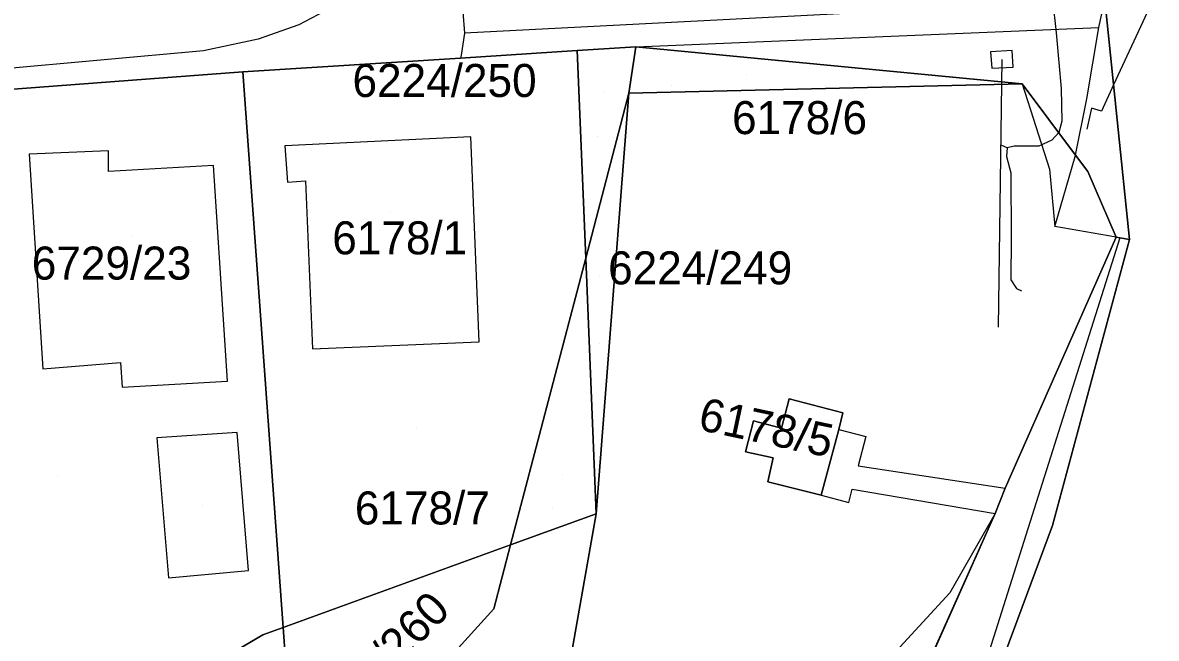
# Model space of a CAD drawing. Extents: x -266199 to -261993, y -1239047 to -1235108.
# Drawn here: x -263970.2 to -263901.5, y -1236261.5 to -1236224.3 of the extents above; entities that cross this region are included whole.
import ezdxf

# ---------------------------------------------------------------- set-up
doc = ezdxf.new("R2010")
doc.units = 0
for name, color, linetype in [('body_kn', 7, 'Continuous'), ('kladpar_druhypozemkov', 7, 'Continuous'), ('kladpar_hranice', 7, 'Continuous'), ('kladpar_parcelnecisla', 7, 'Continuous'), ('kladpar_plochy', 7, 'Continuous'), ('kladpar_sipky', 7, 'Continuous'), ('linie', 7, 'Continuous'), ('tarchy_linie', 7, 'Continuous'), ('zappar_hrandruhpozemk', 7, 'Continuous')]:
    doc.layers.add(name, color=color, linetype=linetype)

msp = doc.modelspace()

# ---------------------------------------------------------------- linework, layer by layer
at = {"layer": 'body_kn'}
for p, q in [((-263953.46, -1236224.39), (-263953.46, -1236224.39)), ((-263943.43, -1236224.89), (-263943.43, -1236224.89)), ((-263907.61, -1236224.67), (-263907.61, -1236224.67)), ((-263905.01, -1236224.56), (-263905.01, -1236224.56)), ((-263905.01, -1236224.56), (-263905.01, -1236224.56)), ((-263955.93, -1236225.26), (-263955.93, -1236225.26)), ((-263907.56, -1236225.09), (-263907.56, -1236225.09)), ((-263959.24, -1236225.96), (-263959.24, -1236225.96)), ((-263943.64, -1236226.23), (-263943.64, -1236226.23)), ((-263936.6, -1236225.95), (-263936.6, -1236225.95)), ((-263936.6, -1236225.95), (-263936.6, -1236225.95)), ((-263933.05, -1236225.73), (-263933.05, -1236225.73)), ((-263933.05, -1236225.73), (-263933.05, -1236225.73)), ((-263911.56, -1236226.02), (-263911.56, -1236226.02)), ((-263911.56, -1236226.02), (-263911.56, -1236226.02)), ((-263910.25, -1236225.94), (-263910.25, -1236225.94)), ((-263943.67, -1236226.4), (-263943.67, -1236226.4)), ((-263910.88, -1236226.48), (-263910.88, -1236226.48)), ((-263910.19, -1236226.95), (-263910.19, -1236226.95)), ((-263956.86, -1236227.23), (-263956.86, -1236227.23)), ((-263956.86, -1236227.23), (-263956.86, -1236227.23)), ((-263911.49, -1236227.01), (-263911.49, -1236227.01)), ((-263909.64, -1236227.97), (-263909.64, -1236227.97)), ((-263909.64, -1236227.97), (-263909.64, -1236227.97)), ((-263907.28, -1236228.25), (-263907.28, -1236228.25)), ((-263904.11, -1236228.02), (-263904.11, -1236228.02)), ((-263933.47, -1236228.53), (-263933.47, -1236228.53)), ((-263933.47, -1236228.53), (-263933.47, -1236228.53)), ((-263905.74, -1236228.87), (-263905.74, -1236228.87)), ((-263905.45, -1236229.43), (-263905.45, -1236229.43)), ((-263904.85, -1236229.61), (-263904.85, -1236229.61)), ((-263907.25, -1236230.23), (-263907.25, -1236230.23)), ((-263907.43, -1236230.92), (-263907.43, -1236230.92)), ((-263907.43, -1236230.92), (-263907.43, -1236230.92)), ((-263905.74, -1236230.7), (-263905.74, -1236230.7)), ((-263954.32, -1236231.72), (-263954.32, -1236231.72)), ((-263943.05, -1236231.17), (-263943.05, -1236231.17)), ((-263910.87, -1236231.7), (-263910.87, -1236231.7)), ((-263910.14, -1236231.74), (-263910.14, -1236231.74)), ((-263908.64, -1236231.73), (-263908.64, -1236231.73)), ((-263907.85, -1236231.37), (-263907.85, -1236231.37)), ((-263969.8, -1236232.23), (-263969.8, -1236232.23)), ((-263965.01, -1236232.02), (-263965.01, -1236232.02)), ((-263910.59, -1236232.37), (-263910.59, -1236232.37)), ((-263910.55, -1236231.84), (-263910.55, -1236231.84)), ((-263910.55, -1236231.84), (-263910.55, -1236231.84)), ((-263906.44, -1236232.37), (-263906.44, -1236232.37)), ((-263906.42, -1236232.28), (-263906.42, -1236232.28)), ((-263906.42, -1236232.28), (-263906.42, -1236232.28)), ((-263958.64, -1236232.91), (-263958.64, -1236232.91)), ((-263908, -1236233.13), (-263908, -1236233.13)), ((-263965, -1236233.28), (-263965, -1236233.28)), ((-263910.34, -1236233.36), (-263910.34, -1236233.36)), ((-263905.67, -1236233.28), (-263905.67, -1236233.28)), ((-263954.15, -1236233.92), (-263954.15, -1236233.92)), ((-263953.06, -1236233.84), (-263953.06, -1236233.84)), ((-263907.66, -1236236.61), (-263907.66, -1236236.61)), ((-263907.66, -1236236.61), (-263907.66, -1236236.61)), ((-263910.31, -1236237.32), (-263910.31, -1236237.32)), ((-263903.96, -1236237.26), (-263903.96, -1236237.26)), ((-263903.96, -1236237.26), (-263903.96, -1236237.26)), ((-263903.74, -1236237.3), (-263903.74, -1236237.3)), ((-263903.74, -1236237.3), (-263903.74, -1236237.3)), ((-263903.15, -1236237.4), (-263903.15, -1236237.4)), ((-263936.09, -1236238.52), (-263936.09, -1236238.52)), ((-263936.09, -1236238.52), (-263936.09, -1236238.52)), ((-263910.34, -1236239.83), (-263910.34, -1236239.83)), ((-263909.99, -1236240.36), (-263909.99, -1236240.36)), ((-263909.68, -1236240.5), (-263909.68, -1236240.5)), ((-263911.1, -1236242.7), (-263911.1, -1236242.7)), ((-263952.64, -1236244.01), (-263952.64, -1236244.01)), ((-263942.54, -1236243.59), (-263942.54, -1236243.59)), ((-263942.54, -1236243.59), (-263942.54, -1236243.59)), ((-263968.98, -1236245.23), (-263968.98, -1236245.23)), ((-263964.28, -1236244.85), (-263964.28, -1236244.85)), ((-263957.8, -1236245.97), (-263957.8, -1236245.97)), ((-263957.8, -1236245.97), (-263957.8, -1236245.97)), ((-263964.17, -1236246.33), (-263964.17, -1236246.33)), ((-263923.76, -1236247.05), (-263923.76, -1236247.05)), ((-263920.52, -1236247.89), (-263920.52, -1236247.89)), ((-263925.92, -1236248.38), (-263925.92, -1236248.38)), ((-263924.22, -1236248.82), (-263924.22, -1236248.82)), ((-263920.76, -1236248.89), (-263920.76, -1236248.89)), ((-263920.76, -1236248.89), (-263920.76, -1236248.89)), ((-263962.08, -1236249.4), (-263962.08, -1236249.4)), ((-263957.2, -1236249.09), (-263957.2, -1236249.09)), ((-263919.12, -1236249.33), (-263919.12, -1236249.33)), ((-263926.4, -1236250.25), (-263926.4, -1236250.25)), ((-263924.74, -1236250.61), (-263924.74, -1236250.61)), ((-263919.58, -1236251.1), (-263919.58, -1236251.1)), ((-263925.06, -1236252.06), (-263925.06, -1236252.06)), ((-263921.83, -1236252.88), (-263921.83, -1236252.88)), ((-263921.83, -1236252.88), (-263921.83, -1236252.88)), ((-263919.94, -1236252.51), (-263919.94, -1236252.51)), ((-263910.67, -1236252.45), (-263910.67, -1236252.45)), ((-263920.15, -1236253.31), (-263920.15, -1236253.31)), ((-263935.46, -1236254.01), (-263935.46, -1236254.01)), ((-263935.46, -1236254.01), (-263935.46, -1236254.01)), ((-263911.28, -1236253.99), (-263911.28, -1236253.99)), ((-263911.28, -1236253.99), (-263911.28, -1236253.99)), ((-263907.81, -1236254.71), (-263907.81, -1236254.71)), ((-263940.64, -1236255.89), (-263940.64, -1236255.89)), ((-263956.52, -1236257.44), (-263956.52, -1236257.44)), ((-263956.52, -1236257.44), (-263956.52, -1236257.44)), ((-263961.37, -1236257.89), (-263961.37, -1236257.89)), ((-263914.04, -1236258.79), (-263914.04, -1236258.79)), ((-263941.66, -1236259.76), (-263941.66, -1236259.76)), ((-263954.42, -1236260.88), (-263954.42, -1236260.88)), ((-263954.42, -1236260.88), (-263954.42, -1236260.88)), ((-263955.66, -1236261.33), (-263955.66, -1236261.33))]:
    msp.add_line(p, q, dxfattribs=at)
at = {"layer": 'kladpar_druhypozemkov'}
for p, q in [((-263930.92, -1236228.04), (-263930.92, -1236228.04)), ((-263934.97, -1236228.42), (-263934.97, -1236228.42)), ((-263947.89, -1236235.68), (-263947.89, -1236235.68)), ((-263963.58, -1236237.23), (-263963.58, -1236237.23)), ((-263935.28, -1236239.64), (-263935.28, -1236239.64)), ((-263946.36, -1236248.86), (-263946.36, -1236248.86)), ((-263923.09, -1236248.82), (-263923.09, -1236248.82)), ((-263968.06, -1236251.67), (-263968.06, -1236251.67)), ((-263937.52, -1236251.64), (-263937.52, -1236251.64)), ((-263959.31, -1236253.5), (-263959.31, -1236253.5))]:
    msp.add_line(p, q, dxfattribs=at)
at = {"layer": 'kladpar_hranice'}
for p, q in [((-263936.09, -1236238.52), (-263936.6, -1236225.95)), ((-263936.6, -1236225.95), (-263936.09, -1236238.52)), ((-263954.42, -1236260.88), (-263956.86, -1236227.23)), ((-263933.47, -1236228.53), (-263909.64, -1236227.97)), ((-263936.09, -1236238.52), (-263933.47, -1236228.53)), ((-263940.64, -1236255.89), (-263936.09, -1236238.52)), ((-263936.09, -1236238.52), (-263940.64, -1236255.89)), ((-263936.09, -1236238.52), (-263935.46, -1236254.01)), ((-263935.46, -1236254.01), (-263940.64, -1236255.89)), ((-263940.64, -1236255.89), (-263935.46, -1236254.01)), ((-263940.64, -1236255.89), (-263954.42, -1236260.88)), ((-263954.42, -1236260.88), (-263940.64, -1236255.89))]:
    msp.add_line(p, q, dxfattribs=at)
for points in [[(-263939.74, -1236296.32), (-263935.82, -1236297.03), (-263934.58, -1236297.27), (-263923.4, -1236283.81), (-263912.8, -1236268.14), (-263907.81, -1236254.71), (-263903.15, -1236237.4), (-263904.63, -1236222.89), (-263904.13, -1236219.7), (-263903.08, -1236212.9), (-263903.59, -1236195.15), (-263904.36, -1236178.51)], [(-263941.74, -1236180.26), (-263941.12, -1236196.31), (-263940.72, -1236210.42), (-263942.15, -1236214.98), (-263943.73, -1236218.25), (-263943.53, -1236223.61), (-263940.64, -1236223.44), (-263927.94, -1236222.73), (-263917.94, -1236221.26), (-263914.48, -1236220.37), (-263904.13, -1236219.7), (-263904.63, -1236222.89), (-263903.15, -1236237.4), (-263903.74, -1236237.3), (-263903.96, -1236237.26)], [(-263909.64, -1236227.97), (-263933.05, -1236225.73), (-263936.6, -1236225.95), (-263943.67, -1236226.4), (-263956.86, -1236227.23), (-263975.06, -1236228.6), (-263984.76, -1236229.36), (-263991.46, -1236229.73), (-263998.08, -1236230.62)], [(-263956.86, -1236227.23), (-263943.67, -1236226.4), (-263936.6, -1236225.95)], [(-263936.6, -1236225.95), (-263933.05, -1236225.73), (-263933.47, -1236228.53), (-263936.09, -1236238.52)], [(-263933.05, -1236225.73), (-263909.64, -1236227.97), (-263933.47, -1236228.53), (-263933.05, -1236225.73)], [(-263975.06, -1236228.6), (-263956.86, -1236227.23), (-263954.42, -1236260.88)], [(-263909.64, -1236227.97), (-263906.42, -1236232.28), (-263905.67, -1236233.28), (-263903.96, -1236237.26)], [(-263903.96, -1236237.26), (-263905.67, -1236233.28), (-263906.42, -1236232.28), (-263909.64, -1236227.97)], [(-263971.35, -1236293.7), (-263937.45, -1236265.34), (-263935.46, -1236254.01), (-263933.47, -1236228.53)], [(-263933.47, -1236228.53), (-263935.46, -1236254.01), (-263936.09, -1236238.52)], [(-263903.96, -1236237.26), (-263910.67, -1236252.45), (-263911.28, -1236253.99), (-263916.97, -1236266.71), (-263925.84, -1236279.74), (-263935.1, -1236291.13), (-263939.74, -1236296.32)], [(-263934.58, -1236297.27), (-263935.82, -1236297.03), (-263939.74, -1236296.32), (-263935.1, -1236291.13), (-263925.84, -1236279.74), (-263916.97, -1236266.71), (-263911.28, -1236253.99), (-263910.67, -1236252.45), (-263903.96, -1236237.26), (-263903.74, -1236237.3), (-263903.15, -1236237.4), (-263907.81, -1236254.71), (-263912.8, -1236268.14), (-263923.4, -1236283.81), (-263934.58, -1236297.27)], [(-263925.06, -1236252.06), (-263921.83, -1236252.88), (-263920.76, -1236248.89), (-263920.52, -1236247.89), (-263923.76, -1236247.05), (-263924.22, -1236248.82), (-263925.92, -1236248.38), (-263926.4, -1236250.25), (-263924.74, -1236250.61), (-263925.06, -1236252.06)], [(-263921.83, -1236252.88), (-263925.06, -1236252.06), (-263924.74, -1236250.61), (-263926.4, -1236250.25), (-263925.92, -1236248.38), (-263924.22, -1236248.82), (-263923.76, -1236247.05), (-263920.52, -1236247.89), (-263920.76, -1236248.89), (-263921.83, -1236252.88)], [(-263935.46, -1236254.01), (-263937.45, -1236265.34), (-263971.35, -1236293.7)], [(-263940.64, -1236255.89), (-263941.66, -1236259.76), (-263953.55, -1236272.88), (-263954.42, -1236260.88)], [(-263953.55, -1236272.88), (-263941.66, -1236259.76), (-263940.64, -1236255.89)], [(-263954.42, -1236260.88), (-263953.55, -1236272.88), (-263971.35, -1236293.7)], [(-263954.42, -1236260.88), (-263955.66, -1236261.33), (-263963.32, -1236265.85)], [(-263963.32, -1236265.85), (-263955.66, -1236261.33), (-263954.42, -1236260.88)]]:
    msp.add_lwpolyline(points, dxfattribs=at)
at = {"layer": 'kladpar_plochy'}
for p, q in [((-263903.15, -1236237.4), (-263904.63, -1236222.89)), ((-263933.47, -1236228.53), (-263909.64, -1236227.97)), ((-263909.64, -1236227.97), (-263906.42, -1236232.28)), ((-263935.46, -1236254.01), (-263933.47, -1236228.53)), ((-263906.42, -1236232.28), (-263905.67, -1236233.28)), ((-263905.67, -1236233.28), (-263903.96, -1236237.26)), ((-263903.96, -1236237.26), (-263910.67, -1236252.45)), ((-263907.81, -1236254.71), (-263903.15, -1236237.4)), ((-263923.76, -1236247.05), (-263924.22, -1236248.82)), ((-263920.52, -1236247.89), (-263923.76, -1236247.05)), ((-263920.76, -1236248.89), (-263920.52, -1236247.89)), ((-263925.92, -1236248.38), (-263926.4, -1236250.25)), ((-263924.22, -1236248.82), (-263925.92, -1236248.38)), ((-263921.83, -1236252.88), (-263920.76, -1236248.89)), ((-263926.4, -1236250.25), (-263924.74, -1236250.61)), ((-263924.74, -1236250.61), (-263925.06, -1236252.06)), ((-263925.06, -1236252.06), (-263921.83, -1236252.88)), ((-263910.67, -1236252.45), (-263911.28, -1236253.99)), ((-263937.45, -1236265.34), (-263935.46, -1236254.01)), ((-263911.28, -1236253.99), (-263916.97, -1236266.71)), ((-263912.8, -1236268.14), (-263907.81, -1236254.71))]:
    msp.add_line(p, q, dxfattribs=at)
msp.add_lwpolyline([(-263941.74, -1236180.26), (-263941.12, -1236196.31), (-263940.72, -1236210.42), (-263942.15, -1236214.98), (-263943.73, -1236218.25), (-263943.53, -1236223.61), (-263940.64, -1236223.44), (-263927.94, -1236222.73), (-263917.94, -1236221.26), (-263914.48, -1236220.37), (-263904.13, -1236219.7), (-263904.63, -1236222.89), (-263903.15, -1236237.4), (-263903.74, -1236237.3), (-263903.96, -1236237.26), (-263905.67, -1236233.28), (-263906.42, -1236232.28), (-263909.64, -1236227.97), (-263933.05, -1236225.73), (-263936.6, -1236225.95), (-263943.67, -1236226.4), (-263956.86, -1236227.23), (-263975.06, -1236228.6)], dxfattribs=at)
for points in [[(-263956.86, -1236227.23), (-263943.67, -1236226.4), (-263936.6, -1236225.95), (-263936.09, -1236238.52), (-263940.64, -1236255.89), (-263954.42, -1236260.88)], [(-263936.6, -1236225.95), (-263933.05, -1236225.73), (-263933.47, -1236228.53), (-263936.09, -1236238.52)], [(-263933.05, -1236225.73), (-263909.64, -1236227.97), (-263933.47, -1236228.53)], [(-263975.06, -1236228.6), (-263956.86, -1236227.23), (-263954.42, -1236260.88), (-263955.66, -1236261.33), (-263963.32, -1236265.85), (-263970.63, -1236266.23), (-263970.47, -1236269.48), (-263969.36, -1236269.42), (-263969.55, -1236269.53), (-263972.72, -1236270.21), (-263973.52, -1236255.75)], [(-263936.09, -1236238.52), (-263933.47, -1236228.53), (-263935.46, -1236254.01)], [(-263934.58, -1236297.27), (-263935.82, -1236297.03), (-263939.74, -1236296.32), (-263935.1, -1236291.13), (-263925.84, -1236279.74), (-263916.97, -1236266.71), (-263911.28, -1236253.99), (-263910.67, -1236252.45), (-263903.96, -1236237.26), (-263903.74, -1236237.3), (-263903.15, -1236237.4), (-263907.81, -1236254.71), (-263912.8, -1236268.14), (-263923.4, -1236283.81)], [(-263936.09, -1236238.52), (-263935.46, -1236254.01), (-263940.64, -1236255.89)], [(-263921.83, -1236252.88), (-263925.06, -1236252.06), (-263924.74, -1236250.61), (-263926.4, -1236250.25), (-263925.92, -1236248.38), (-263924.22, -1236248.82), (-263923.76, -1236247.05), (-263920.52, -1236247.89), (-263920.76, -1236248.89)], [(-263953.55, -1236272.88), (-263941.66, -1236259.76), (-263940.64, -1236255.89), (-263935.46, -1236254.01), (-263937.45, -1236265.34), (-263971.35, -1236293.7)], [(-263954.42, -1236260.88), (-263940.64, -1236255.89), (-263941.66, -1236259.76), (-263953.55, -1236272.88)], [(-263969.55, -1236269.53), (-263969.36, -1236269.42), (-263962.64, -1236269.04), (-263962.67, -1236265.82), (-263963.32, -1236265.85), (-263955.66, -1236261.33), (-263954.42, -1236260.88), (-263953.55, -1236272.88), (-263971.35, -1236293.7)]]:
    msp.add_lwpolyline(points, close=True, dxfattribs=at)
at = {"layer": 'kladpar_sipky'}
for p, q in [((-263926.36, -1236227.39), (-263926.36, -1236227.39)), ((-263935.37, -1236231.14), (-263935.37, -1236231.14)), ((-263935.27, -1236243.71), (-263935.27, -1236243.71)), ((-263938.11, -1236253.65), (-263938.11, -1236253.65))]:
    msp.add_line(p, q, dxfattribs=at)
at = {"layer": 'linie'}
msp.add_line((-263910.88, -1236226.48), (-263911.1, -1236242.7), dxfattribs=at)
at = {"layer": 'tarchy_linie'}
for points in [[(-263947.81, -1235901.98), (-263947.69, -1235903.35), (-263943.6, -1235905.78), (-263940.03, -1235926.05), (-263933.41, -1235953.88), (-263921.52, -1235995.74), (-263913.18, -1236027.02), (-263907.3, -1236058.84), (-263905.11, -1236095.12), (-263903.91, -1236139.53), (-263902.79, -1236171.66), (-263901.68, -1236205.85), (-263901.52, -1236222.46), (-263904.11, -1236228.02), (-263904.85, -1236229.61), (-263905.45, -1236229.43), (-263905.74, -1236230.7)], [(-263907.79, -1236223.05), (-263907.61, -1236224.67), (-263907.56, -1236225.09), (-263907.28, -1236228.25), (-263907.25, -1236230.23), (-263907.43, -1236230.92)], [(-263907.43, -1236230.92), (-263907.85, -1236231.37), (-263908.64, -1236231.73), (-263910.14, -1236231.74), (-263910.55, -1236231.84), (-263910.87, -1236231.7)], [(-263910.55, -1236231.84), (-263910.59, -1236232.37), (-263910.34, -1236233.36), (-263910.31, -1236237.32), (-263910.34, -1236239.83), (-263909.99, -1236240.36), (-263909.68, -1236240.5)]]:
    msp.add_lwpolyline(points, dxfattribs=at)
at = {"layer": 'zappar_hrandruhpozemk'}
for p, q in [((-263904.63, -1236222.89), (-263943.43, -1236224.89)), ((-263905.01, -1236224.56), (-263904.63, -1236222.89)), ((-263933.05, -1236225.73), (-263905.01, -1236224.56)), ((-263905.74, -1236228.87), (-263905.01, -1236224.56)), ((-263959.24, -1236225.96), (-263975.34, -1236227.42)), ((-263910.25, -1236225.94), (-263911.56, -1236226.02)), ((-263909.64, -1236227.97), (-263908, -1236233.13)), ((-263906.42, -1236232.28), (-263905.74, -1236228.87)), ((-263942.54, -1236243.59), (-263943.05, -1236231.17)), ((-263969.8, -1236232.23), (-263968.98, -1236245.23)), ((-263908, -1236233.13), (-263907.66, -1236236.61)), ((-263903.96, -1236237.26), (-263907.66, -1236236.61)), ((-263903.74, -1236237.3), (-263913.54, -1236268.33)), ((-263962.08, -1236249.4), (-263961.37, -1236257.89)), ((-263919.58, -1236251.1), (-263910.67, -1236252.45)), ((-263919.94, -1236252.51), (-263911.28, -1236253.99)), ((-263911.28, -1236253.99), (-263914.04, -1236258.79)), ((-263961.37, -1236257.89), (-263956.52, -1236257.44)), ((-263914.04, -1236258.79), (-263919.77, -1236265.03))]:
    msp.add_line(p, q, dxfattribs=at)
for points in [[(-263944.26, -1236150.19), (-263943, -1236180.37), (-263942.51, -1236196.51), (-263942.06, -1236210.22), (-263943.2, -1236213.94), (-263945.42, -1236217.79), (-263945.92, -1236218.44), (-263948.41, -1236221.01), (-263950.79, -1236222.97), (-263953.46, -1236224.39), (-263955.93, -1236225.26), (-263959.24, -1236225.96)], [(-263943.53, -1236223.61), (-263943.43, -1236224.89), (-263943.64, -1236226.23), (-263943.67, -1236226.4)], [(-263911.56, -1236226.02), (-263911.49, -1236227.01), (-263910.19, -1236226.95), (-263910.25, -1236225.94)], [(-263943.05, -1236231.17), (-263954.32, -1236231.72), (-263954.15, -1236233.92), (-263953.06, -1236233.84), (-263952.64, -1236244.01), (-263942.54, -1236243.59)], [(-263957.8, -1236245.97), (-263958.64, -1236232.91), (-263965, -1236233.28), (-263965.01, -1236232.02), (-263969.8, -1236232.23)], [(-263907.66, -1236236.61), (-263906.44, -1236232.37), (-263906.42, -1236232.28)], [(-263968.98, -1236245.23), (-263964.28, -1236244.85), (-263964.17, -1236246.33), (-263957.8, -1236245.97)], [(-263920.76, -1236248.89), (-263919.12, -1236249.33), (-263919.58, -1236251.1)], [(-263956.52, -1236257.44), (-263957.2, -1236249.09), (-263962.08, -1236249.4)], [(-263921.83, -1236252.88), (-263920.15, -1236253.31), (-263919.94, -1236252.51)]]:
    msp.add_lwpolyline(points, dxfattribs=at)

# ---------------------------------------------------------------- texts
at = {"layer": 'kladpar_parcelnecisla'}
for s, p in [('6224/250', (-263950.218, -1236228.76)), ('6178/6', (-263927.225, -1236231.01)), ('6178/1', (-263951.445, -1236238.29)), ('6729/23', (-263969.649, -1236239.82)), ('6224/249', (-263934.732, -1236240.11)), ('6178/7', (-263950.077, -1236254.65))]:
    msp.add_text(s, height=2, dxfattribs=at).set_placement(p)
for s, rotation, p in [('6178/5', 348, (-263929.35, -1236248.897)), ('6224/260', 45, (-263952.085, -1236267.839))]:
    msp.add_text(s, height=2, rotation=rotation, dxfattribs=at).set_placement(p)

doc.saveas('drawing.dxf')
